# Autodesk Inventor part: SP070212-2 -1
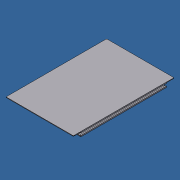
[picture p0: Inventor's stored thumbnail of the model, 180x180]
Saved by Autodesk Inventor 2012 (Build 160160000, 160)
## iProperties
Created: 2012-06
Part Number: SP070212-2 -1
Material: Aluminum-6061
Description: MILL TO SP062512-2-1
Document SubType Name: Modeling
Designer: Administrator
Stock Number: 20.1077 PROFILE 19X270
Density: 2.71 g/cm^3
Mass: 1987.87 g
Surface Area: 4854.26 cm^2
Volume: 733.53 cm^3
FINISH: CLEAR ANODIZED
Author: Administrator
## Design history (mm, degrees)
sketch "Sketch1" dims "d0" = 403.225, "d1" = 0
  geometry: L1 (103.3, 5)-(103.3, -5) reference; L2 (101.3, -7)-(100.091, -7) reference; L3 (98.677, -6.414)-(93.769, -1.506) reference; L4 (91.506, -3.769)-(93.03, -5.293) reference; L5 (92.323, -7)-(87.677, -7) reference; L6 (86.97, -5.293)-(88.494, -3.769) reference; L7 (86.231, -1.506)-(81.323, -6.414) reference; L8 (79.909, -7)-(78.7, -7) reference; L9 (76.7, -5)-(76.7, 5) reference; L10 (78.7, 7)-(79.909, 7) reference; L11 (81.323, 6.414)-(86.231, 1.506) reference; L12 (88.494, 3.769)-(86.97, 5.293) reference; L13 (87.677, 7)-(92.323, 7) reference; L14 (93.03, 5.293)-(91.506, 3.769) reference; L15 (93.769, 1.506)-(98.677, 6.414) reference; L16 (100.091, 7)-(101.3, 7) reference; L17 (-76.7, 5)-(-76.7, -5) reference; L18 (-78.7, -7)-(-79.909, -7) reference; L19 (-81.323, -6.414)-(-86.231, -1.506) reference; L20 (-88.494, -3.769)-(-86.97, -5.293) reference; L21 (-87.677, -7)-(-92.323, -7) reference; L22 (-93.03, -5.293)-(-91.506, -3.769) reference; L23 (-93.769, -1.506)-(-98.677, -6.414) reference; L24 (-100.091, -7)-(-101.3, -7) reference; L25 (-103.3, -5)-(-103.3, 5) reference; L26 (-101.3, 7)-(-100.091, 7) reference; L27 (-98.677, 6.414)-(-93.769, 1.506) reference; L28 (-91.506, 3.769)-(-93.03, 5.293) reference; L29 (-92.323, 7)-(-87.677, 7) reference; L30 (-86.97, 5.293)-(-88.494, 3.769) reference; L31 (-86.231, 1.506)-(-81.323, 6.414) reference; L32 (-79.909, 7)-(-78.7, 7) reference; L33 (33.7, 7)-(56.3, 7) reference; L34 (58.3, 5)-(58.3, -5) reference; L35 (56.3, -7)-(33.7, -7) reference; L36 (31.7, -5)-(31.7, 5) reference; L37 (-11.3, 7)-(11.3, 7) reference; L38 (13.3, 5)-(13.3, -5) reference; L39 (11.3, -7)-(-11.3, -7) reference; L40 (-13.3, -5)-(-13.3, 5) reference; L41 (-56.3, 7)-(-33.7, 7) reference; L42 (-31.7, 5)-(-31.7, -5) reference; L43 (-33.7, -7)-(-56.3, -7) reference; L44 (-58.3, -5)-(-58.3, 5) reference; L45 (135, -4.25)-(130.5, -4.25) reference; L46 (130.5, -4.25)-(130.5, -7) reference; L47 (130.5, -7)-(122.8, -7) reference; L48 (121.8, -6)-(121.8, 6) reference; L49 (122.8, 7)-(130.5, 7) reference; L50 (130.5, 4.25)-(135, 4.25) reference; L51 (135, 4.25)-(135, 9.5) reference; L52 (-135, 9.5)-(135, 9.5) reference; L53 (-135, 4.25)-(-130.5, 4.25) reference; L54 (-130.5, 7)-(-122.8, 7) reference; L55 (-121.8, 6)-(-121.8, -6) reference; L56 (-122.8, -7)-(-130.5, -7) reference; L57 (-130.5, -7)-(-130.5, -4.25) reference; L58 (-130.5, -4.25)-(-135, -4.25) reference; L59 (-135, -9.5)-(-135, -4.25) reference; L60 (-116.6, -9.5)-(-116.6, -5) reference; L61 (-119.3, -5)-(-119.3, 3.5) reference; L62 (-119.3, 3.5)-(-117, 5.8) reference; L63 (-117, 5.8)-(-108, 5.8) reference; L64 (-108, 5.8)-(-105.7, 3.5) reference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; A1 r 2 centre (101.3, 5) between (103.3, 5) and (101.3, 7) reference; A2 r 2 centre (101.3, -5) between (101.3, -7) and (103.3, -5) reference; A3 r 2 centre (100.091, -5) between (98.677, -6.414) and (100.091, -7) reference; A4 r 0.3 centre (93.557, -1.718) between (93.769, -1.506) and (93.287, -1.588) reference; A5 r 3.65 centre (90, 0) between (91.588, -3.287) and (93.287, -1.588) reference; A6 r 0.3 centre (91.718, -3.557) between (91.588, -3.287) and (91.506, -3.769) reference; A7 r 1 centre (92.323, -6) between (92.323, -7) and (93.03, -5.293) reference; A8 r 1 centre (87.677, -6) between (86.97, -5.293) and (87.677, -7) reference; A9 r 0.3 centre (88.282, -3.557) between (88.494, -3.769) and (88.412, -3.287) reference; A10 r 3.65 centre (90, 0) between (86.713, -1.588) and (88.412, -3.287) reference; A11 r 0.3 centre (86.443, -1.718) between (86.713, -1.588) and (86.231, -1.506) reference; A12 r 2 centre (79.909, -5) between (79.909, -7) and (81.323, -6.414) reference; A13 r 2 centre (78.7, -5) between (76.7, -5) and (78.7, -7) reference; A14 r 2 centre (78.7, 5) between (78.7, 7) and (76.7, 5) reference; A15 r 2 centre (79.909, 5) between (81.323, 6.414) and (79.909, 7) reference; A16 r 0.3 centre (86.443, 1.718) between (86.231, 1.506) and (86.713, 1.588) reference; A17 r 3.65 centre (90, 0) between (88.412, 3.287) and (86.713, 1.588) reference; A18 r 0.3 centre (88.282, 3.557) between (88.412, 3.287) and (88.494, 3.769) reference; A19 r 1 centre (87.677, 6) between (87.677, 7) and (86.97, 5.293) reference; A20 r 1 centre (92.323, 6) between (93.03, 5.293) and (92.323, 7) reference; A21 r 0.3 centre (91.718, 3.557) between (91.506, 3.769) and (91.588, 3.287) reference; A22 r 3.65 centre (90, 0) between (93.287, 1.588) and (91.588, 3.287) reference; A23 r 0.3 centre (93.557, 1.718) between (93.287, 1.588) and (93.769, 1.506) reference; A24 r 2 centre (100.091, 5) between (100.091, 7) and (98.677, 6.414) reference; A25 r 2 centre (-78.7, 5) between (-76.7, 5) and (-78.7, 7) reference; A26 r 2 centre (-78.7, -5) between (-78.7, -7) and (-76.7, -5) reference; A27 r 2 centre (-79.909, -5) between (-81.323, -6.414) and (-79.909, -7) reference; A28 r 0.3 centre (-86.443, -1.718) between (-86.231, -1.506) and (-86.713, -1.588) reference; A29 r 3.65 centre (-90, 0) between (-88.412, -3.287) and (-86.713, -1.588) reference; A30 r 0.3 centre (-88.282, -3.557) between (-88.412, -3.287) and (-88.494, -3.769) reference; A31 r 1 centre (-87.677, -6) between (-87.677, -7) and (-86.97, -5.293) reference; A32 r 1 centre (-92.323, -6) between (-93.03, -5.293) and (-92.323, -7) reference; A33 r 0.3 centre (-91.718, -3.557) between (-91.506, -3.769) and (-91.588, -3.287) reference; A34 r 3.65 centre (-90, 0) between (-93.287, -1.588) and (-91.588, -3.287) reference; A35 r 0.3 centre (-93.557, -1.718) between (-93.287, -1.588) and (-93.769, -1.506) reference; A36 r 2 centre (-100.091, -5) between (-100.091, -7) and (-98.677, -6.414) reference; A37 r 2 centre (-101.3, -5) between (-103.3, -5) and (-101.3, -7) reference; A38 r 2 centre (-101.3, 5) between (-101.3, 7) and (-103.3, 5) reference; A39 r 2 centre (-100.091, 5) between (-98.677, 6.414) and (-100.091, 7) reference; A40 r 0.3 centre (-93.557, 1.718) between (-93.769, 1.506) and (-93.287, 1.588) reference; A41 r 3.65 centre (-90, 0) between (-91.588, 3.287) and (-93.287, 1.588) reference; A42 r 0.3 centre (-91.718, 3.557) between (-91.588, 3.287) and (-91.506, 3.769) reference; A43 r 1 centre (-92.323, 6) between (-92.323, 7) and (-93.03, 5.293) reference; A44 r 1 centre (-87.677, 6) between (-86.97, 5.293) and (-87.677, 7) reference; A45 r 0.3 centre (-88.282, 3.557) between (-88.494, 3.769) and (-88.412, 3.287) reference; A46 r 3.65 centre (-90, 0) between (-86.713, 1.588) and (-88.412, 3.287) reference; A47 r 0.3 centre (-86.443, 1.718) between (-86.713, 1.588) and (-86.231, 1.506) reference; A48 r 2 centre (-79.909, 5) between (-79.909, 7) and (-81.323, 6.414) reference; A49 r 2 centre (56.3, 5) between (58.3, 5) and (56.3, 7) reference; A50 r 2 centre (56.3, -5) between (56.3, -7) and (58.3, -5) reference; A51 r 2 centre (33.7, -5) between (31.7, -5) and (33.7, -7) reference; A52 r 2 centre (33.7, 5) between (33.7, 7) and (31.7, 5) reference; A53 r 2 centre (11.3, 5) between (13.3, 5) and (11.3, 7) reference; A54 r 2 centre (11.3, -5) between (11.3, -7) and (13.3, -5) reference; A55 r 2 centre (-11.3, -5) between (-13.3, -5) and (-11.3, -7) reference; A56 r 2 centre (-11.3, 5) between (-11.3, 7) and (-13.3, 5) reference; A57 r 2 centre (-33.7, 5) between (-31.7, 5) and (-33.7, 7) reference; A58 r 2 centre (-33.7, -5) between (-33.7, -7) and (-31.7, -5) reference; A59 r 2 centre (-56.3, -5) between (-58.3, -5) and (-56.3, -7) reference; A60 r 2 centre (-56.3, 5) between (-56.3, 7) and (-58.3, 5) reference; A61 r 1 centre (122.8, -6) between (121.8, -6) and (122.8, -7) reference; A62 r 1 centre (122.8, 6) between (122.8, 7) and (121.8, 6) reference; A63 r 1 centre (-122.8, 6) between (-121.8, 6) and (-122.8, 7) reference; A64 r 1 centre (-122.8, -6) between (-122.8, -7) and (-121.8, -6) reference
  constraints: 248 end point, 128 point on circle, 64 centre point, 44 horizontal, 36 vertical, 360 other
extrude "Extrusion1" new body sketch "Sketch1" stored distance "d0" = 403.225; taper "d1" = 0 deg
sketch "Sketch3"
  geometry: L1 (-31.7, 5)-(-31.7, -5) reference; L2 (-33.7, -7)-(-56.3, -7) reference; L3 (-58.3, -5)-(-58.3, 5) reference; L4 (-56.3, 7)-(-33.7, 7) reference; L5 (13.3, 5)-(13.3, -5) reference; L6 (11.3, -7)-(-11.3, -7) reference; L7 (-13.3, -5)-(-13.3, 5) reference; L8 (-11.3, 7)-(11.3, 7) reference; L9 (58.3, 5)-(58.3, -5) reference; L10 (56.3, -7)-(33.7, -7) reference; L11 (31.7, -5)-(31.7, 5) reference; L12 (33.7, 7)-(56.3, 7) reference; L13 (103.3, 5)-(103.3, -5) reference; L14 (101.3, -7)-(100.091, -7) reference; L15 (98.677, -6.414)-(93.769, -1.506) reference; L16 (91.506, -3.769)-(93.03, -5.293) reference; L17 (92.323, -7)-(87.677, -7) reference; L18 (86.97, -5.293)-(88.494, -3.769) reference; L19 (86.231, -1.506)-(81.323, -6.414) reference; L20 (79.909, -7)-(78.7, -7) reference; L21 (76.7, -5)-(76.7, 5) reference; L22 (78.7, 7)-(79.909, 7) reference; L23 (81.323, 6.414)-(86.231, 1.506) reference; L24 (88.494, 3.769)-(86.97, 5.293) reference; L25 (87.677, 7)-(92.323, 7) reference; L26 (93.03, 5.293)-(91.506, 3.769) reference; L27 (93.769, 1.506)-(98.677, 6.414) reference; L28 (100.091, 7)-(101.3, 7) reference; L29 (-76.7, 5)-(-76.7, -5) reference; L30 (-78.7, -7)-(-79.909, -7) reference; L31 (-81.323, -6.414)-(-86.231, -1.506) reference; L32 (-88.494, -3.769)-(-86.97, -5.293) reference; L33 (-87.677, -7)-(-92.323, -7) reference; L34 (-93.03, -5.293)-(-91.506, -3.769) reference; L35 (-93.769, -1.506)-(-98.677, -6.414) reference; L36 (-100.091, -7)-(-101.3, -7) reference; L37 (-103.3, -5)-(-103.3, 5) reference; L38 (-101.3, 7)-(-100.091, 7) reference; L39 (-98.677, 6.414)-(-93.769, 1.506) reference; L40 (-91.506, 3.769)-(-93.03, 5.293) reference; L41 (-92.323, 7)-(-87.677, 7) reference; L42 (-86.97, 5.293)-(-88.494, 3.769) reference; L43 (-86.231, 1.506)-(-81.323, 6.414) reference; L44 (-79.909, 7)-(-78.7, 7) reference; L45 (-135, 9.5)-(135, 9.5) reference; L46 (135, -9.5)-(-137.59, -9.5); L47 (-137.59, -9.5)-(-137.59, 7.1); L48 (-137.59, 7.1)-(135, 7.1); L49 (135, 7.1)-(135, -9.5); A1 r 2 centre (-33.7, 5) between (-31.7, 5) and (-33.7, 7) reference; A2 r 2 centre (-33.7, -5) between (-33.7, -7) and (-31.7, -5) reference; A3 r 2 centre (-56.3, -5) between (-58.3, -5) and (-56.3, -7) reference; A4 r 2 centre (-56.3, 5) between (-56.3, 7) and (-58.3, 5) reference; A5 r 2 centre (11.3, 5) between (13.3, 5) and (11.3, 7) reference; A6 r 2 centre (11.3, -5) between (11.3, -7) and (13.3, -5) reference; A7 r 2 centre (-11.3, -5) between (-13.3, -5) and (-11.3, -7) reference; A8 r 2 centre (-11.3, 5) between (-11.3, 7) and (-13.3, 5) reference; A9 r 2 centre (56.3, 5) between (58.3, 5) and (56.3, 7) reference; A10 r 2 centre (56.3, -5) between (56.3, -7) and (58.3, -5) reference; A11 r 2 centre (33.7, -5) between (31.7, -5) and (33.7, -7) reference; A12 r 2 centre (33.7, 5) between (33.7, 7) and (31.7, 5) reference; A13 r 2 centre (101.3, -5) between (101.3, -7) and (103.3, -5) reference; A14 r 2 centre (100.091, -5) between (98.677, -6.414) and (100.091, -7) reference; A15 r 0.3 centre (93.557, -1.718) between (93.769, -1.506) and (93.287, -1.588) reference; A16 r 3.65 centre (90, 0) between (91.588, -3.287) and (93.287, -1.588) reference; A17 r 0.3 centre (91.718, -3.557) between (91.588, -3.287) and (91.506, -3.769) reference; A18 r 1 centre (92.323, -6) between (92.323, -7) and (93.03, -5.293) reference; A19 r 1 centre (87.677, -6) between (86.97, -5.293) and (87.677, -7) reference; A20 r 0.3 centre (88.282, -3.557) between (88.494, -3.769) and (88.412, -3.287) reference; A21 r 3.65 centre (90, 0) between (86.713, -1.588) and (88.412, -3.287) reference; A22 r 0.3 centre (86.443, -1.718) between (86.713, -1.588) and (86.231, -1.506) reference; A23 r 2 centre (79.909, -5) between (79.909, -7) and (81.323, -6.414) reference; A24 r 2 centre (78.7, -5) between (76.7, -5) and (78.7, -7) reference; A25 r 2 centre (78.7, 5) between (78.7, 7) and (76.7, 5) reference; A26 r 2 centre (79.909, 5) between (81.323, 6.414) and (79.909, 7) reference; A27 r 0.3 centre (86.443, 1.718) between (86.231, 1.506) and (86.713, 1.588) reference; A28 r 3.65 centre (90, 0) between (88.412, 3.287) and (86.713, 1.588) reference; A29 r 0.3 centre (88.282, 3.557) between (88.412, 3.287) and (88.494, 3.769) reference; A30 r 1 centre (87.677, 6) between (87.677, 7) and (86.97, 5.293) reference; A31 r 1 centre (92.323, 6) between (93.03, 5.293) and (92.323, 7) reference; A32 r 0.3 centre (91.718, 3.557) between (91.506, 3.769) and (91.588, 3.287) reference; A33 r 3.65 centre (90, 0) between (93.287, 1.588) and (91.588, 3.287) reference; A34 r 0.3 centre (93.557, 1.718) between (93.287, 1.588) and (93.769, 1.506) reference; A35 r 2 centre (100.091, 5) between (100.091, 7) and (98.677, 6.414) reference; A36 r 2 centre (101.3, 5) between (103.3, 5) and (101.3, 7) reference; A37 r 2 centre (-78.7, -5) between (-78.7, -7) and (-76.7, -5) reference; A38 r 2 centre (-79.909, -5) between (-81.323, -6.414) and (-79.909, -7) reference; A39 r 0.3 centre (-86.443, -1.718) between (-86.231, -1.506) and (-86.713, -1.588) reference; A40 r 3.65 centre (-90, 0) between (-88.412, -3.287) and (-86.713, -1.588) reference; A41 r 0.3 centre (-88.282, -3.557) between (-88.412, -3.287) and (-88.494, -3.769) reference; A42 r 1 centre (-87.677, -6) between (-87.677, -7) and (-86.97, -5.293) reference; A43 r 1 centre (-92.323, -6) between (-93.03, -5.293) and (-92.323, -7) reference; A44 r 0.3 centre (-91.718, -3.557) between (-91.506, -3.769) and (-91.588, -3.287) reference; A45 r 3.65 centre (-90, 0) between (-93.287, -1.588) and (-91.588, -3.287) reference; A46 r 0.3 centre (-93.557, -1.718) between (-93.287, -1.588) and (-93.769, -1.506) reference; A47 r 2 centre (-100.091, -5) between (-100.091, -7) and (-98.677, -6.414) reference; A48 r 2 centre (-101.3, -5) between (-103.3, -5) and (-101.3, -7) reference; A49 r 2 centre (-101.3, 5) between (-101.3, 7) and (-103.3, 5) reference; A50 r 2 centre (-100.091, 5) between (-98.677, 6.414) and (-100.091, 7) reference; A51 r 0.3 centre (-93.557, 1.718) between (-93.769, 1.506) and (-93.287, 1.588) reference; A52 r 3.65 centre (-90, 0) between (-91.588, 3.287) and (-93.287, 1.588) reference; A53 r 0.3 centre (-91.718, 3.557) between (-91.588, 3.287) and (-91.506, 3.769) reference; A54 r 1 centre (-92.323, 6) between (-92.323, 7) and (-93.03, 5.293) reference; A55 r 1 centre (-87.677, 6) between (-86.97, 5.293) and (-87.677, 7) reference; A56 r 0.3 centre (-88.282, 3.557) between (-88.494, 3.769) and (-88.412, 3.287) reference; A57 r 3.65 centre (-90, 0) between (-86.713, 1.588) and (-88.412, 3.287) reference; A58 r 0.3 centre (-86.443, 1.718) between (-86.713, 1.588) and (-86.231, 1.506) reference; A59 r 2 centre (-79.909, 5) between (-79.909, 7) and (-81.323, 6.414) reference; A60 r 2 centre (-78.7, 5) between (-76.7, 5) and (-78.7, 7) reference; 1 further point
  constraints: 8 end point, 2 parallel, 1 horizontal, 1 perpendicular
  dimensions: "d15" = 2.4 distance between parallel lines of L48 L45
extrude "Extrusion2" cut sketch "Sketch3" distance "d16" = 30.1125; taper "d17" = 0 deg
mirror "Mirror1"
thread "Thread1" dims "d18" = 25.4, "d19" = 0
thread "Thread2" dims "d20" = 25.4, "d21" = 0
thread "Thread3" dims "d22" = 25.4, "d23" = 0
thread "Thread4" dims "d24" = 25.4, "d25" = 0
thread "Thread5" dims "d26" = 25.4, "d27" = 0
thread "Thread6" dims "d28" = 25.4, "d29" = 0
thread "Thread7" dims "d30" = 25.4, "d31" = 0
thread "Thread8" dims "d32" = 25.4, "d33" = 0
fillet "Fillet1" dims "d34" = 2.5
thread "Thread9" dims "d35" = 25.4, "d36" = 0
thread "Thread10" dims "d37" = 25.4, "d38" = 0
thread "Thread11" dims "d39" = 25.4, "d40" = 0
thread "Thread12" dims "d41" = 25.4, "d42" = 0
thread "Thread13" dims "d43" = 25.4, "d44" = 0
thread "Thread14" dims "d45" = 25.4, "d46" = 0
thread "Thread15" dims "d47" = 25.4, "d48" = 0
thread "Thread16" dims "d49" = 25.4, "d50" = 0
sketch "Sketch4"
  geometry: L1 (267.5, 2.5)-(267.5, 400.725) reference; L2 (204.275, 284.353)-(204.275, 118.872); L3 (240.724, 121.613)-(240.724, 281.613); L4 (210.625, 284.353)-(210.625, 281.613); L5 (240.724, 281.613)-(240.724, 284.353); L6 (234.374, 284.353)-(234.374, 281.613); L7 (240.724, 118.872)-(240.724, 121.613); L8 (234.374, 118.872)-(234.374, 121.613); L9 (210.625, 118.872)-(210.625, 121.613); L10 (210.625, 121.613)-(219.325, 121.613); L11 (225.675, 121.613)-(234.374, 121.613); L12 (234.374, 281.613)-(225.675, 281.613); L13 (219.325, 281.613)-(210.625, 281.613); A1 r 3.175 centre (207.45, 118.872) between (204.275, 118.872) and (210.625, 118.872); A2 r 3.175 centre (237.549, 118.872) between (234.374, 118.872) and (240.724, 118.872); A3 r 3.175 centre (207.45, 284.353) between (210.625, 284.353) and (204.275, 284.353); A4 r 3.175 centre (237.549, 284.353) between (240.724, 284.353) and (234.374, 284.353); A5 r 3.175 centre (222.5, 121.613) between (219.325, 121.613) and (225.675, 121.613); A6 r 3.175 centre (222.5, 281.613) between (225.675, 281.613) and (219.325, 281.613); 6 further points
  constraints: 24 end point, 12 point on circle, 10 tangent, 9 horizontal alignment, 9 parallel, 6 centre point, 4 perpendicular, 2 coincident, 2 horizontal, 2 midpoint, 2 vertical alignment
  dimensions: "d51" = 160 distance of L3.start L3.end; "d52" = 36.449 distance between parallel lines of L3 L2; "d53" = 6.35 diameter of A4; "d54" = 6.35 diameter of A3 (= d53); "d55" = 6.35 diameter of A1 (= d54); "d56" = 6.35 diameter of A2 (= d55); "d57" = 165.481 distance of A3.centre A1.centre; "d58" = 82.7405 vertical distance of A1.centre point (222.5, 201.613) (= 0.5 x d57); "d59" = 6.35 diameter of A6; "d60" = 6.35 diameter of A5; "d61" = 15.0495 horizontal distance of A5.centre A1.centre; "d62" = 15.0495 horizontal distance of A4.centre point (222.5, 281.613); "d63" = 2.7405 vertical distance of A2.centre A5.centre; "d64" = 2.7405 vertical distance of A4.centre point (222.5, 281.613); "d65" = 8.6995 distance of L13.start L4.end; "d66" = 8.6995 distance of L11.start L8.end; "d67" = 45 distance from line of point (222.5, 201.613) L1
extrude "Extrusion3" cut sketch "Sketch4" distance "d68" = 13.208; taper "d69" = 0 deg
sketch "Sketch5"
  geometry: C1 r 1.621 at (18.4, -251.5) reference; C2 r 1.621 at (18.4, -91.5) reference; 3 further points
  constraints: 2 coincident
hole "Hole2" sketch "Sketch5" at (18.4, -91.5), (18.4, -251.5) diameter "d70" = 5; stored, may be unused: countersink angle "d74" = 82 deg, drill point angle "d76" = 118 deg; dims "d71" = 19.05, "d72" = 9.525, "d73" = 6.35, "d75" = 25.4
body "Solid1"
node "Reference4"
node "Reference5"
